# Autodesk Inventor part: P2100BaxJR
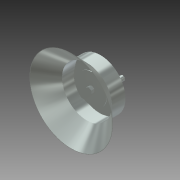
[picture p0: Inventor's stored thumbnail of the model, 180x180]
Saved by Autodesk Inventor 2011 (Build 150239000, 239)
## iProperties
Created: 2014-07
Part Number: P2100BaxJR
Document SubType Name: Modeling
Designer: Evgeny
Density: 1 g/cm^3
Author: Evgeny
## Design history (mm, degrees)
sketch "Эскиз1"
  geometry: L1 (31, 26.833)-(31, -26.833); L2 (-31, -26.833)-(-31, 26.833); C1 r 1.35 at (15, -26); A1 r 41 centre (0, 0) between (31, 26.833) and (-31, 26.833); A2 r 41 centre (0, 0) between (-31, -26.833) and (31, -26.833); 1 further point
  constraints: 4 end point, 4 point on circle, 3 centre point, 1 coincident, 1 parallel
  dimensions: "d1" = 62 distance between parallel lines of L1 L2; "d2" = 31 distance from line of L2 point (0, 0); "d3" = 41 radius of A1; "d4" = 41 radius of A2; "d7" = 2.7 diameter of C1; "d9" = 26 vertical distance of point (0, 0) C1.centre; "d50" = 15 horizontal distance of C1.centre point (0, 0)
extrude "Выдавливание1" new body sketch "Эскиз1" distance "d10" = 1; taper "d11" = 0 deg
sketch "Эскиз2"
  geometry: C1 r 4 at (0, 0); A1 r 41 centre (0, 0) between (31, 26.833) and (-31, 26.833) reference
  constraints: 1 centre point, 1 coincident
  dimensions: "d12" = 8 diameter of C1
extrude "Выдавливание2" join sketch "Эскиз2" distance "d13" = 6; taper "d14" = 0 deg
sketch "Эскиз3"
  geometry: C1 r 4 at (0, 0) reference; C2 r 28 at (0, 0)
  constraints: 1 centre point, 1 coincident
  dimensions: "d15" = 56 diameter of C2
extrude "Выдавливание3" join sketch "Эскиз3" distance "d16" = 1; taper "d17" = 0 deg
sketch "Эскиз4"
  geometry: L1 (5.774, 0)-(2.887, -5); L2 (2.887, -5)-(-2.887, -5); L3 (-2.887, -5)-(-5.774, 0); L4 (-5.774, 0)-(-2.887, 5); L5 (-2.887, 5)-(2.887, 5); L6 (2.887, 5)-(5.774, 0); C1 r 28 at (0, 0) reference; 1 further point
  constraints: 12 end point, 1 coincident, 13 other
  dimensions: "d18" = 10 distance between parallel lines of L2 L5
extrude "Выдавливание4" join sketch "Эскиз4" distance "d19" = 6; taper "d20" = 0 deg
sketch "Эскиз5"
  geometry: C1 r 4 at (0, 0); A1 r 41 centre (0, 0) between (31, 26.833) and (-31, 26.833) reference
  constraints: 1 centre point, 1 coincident
  dimensions: "d21" = 8 diameter of C1
extrude "Выдавливание5" join sketch "Эскиз5" distance "d22" = 7; taper "d23" = 0 deg
sketch "Эскиз6"
  geometry: C1 r 4 at (0, 0) reference; C2 r 47.5 at (0, 0); C3 r 4 at (-15, -26)
  constraints: 2 centre point, 1 coincident
  dimensions: "d24" = 95 diameter of C2; "d33" = 8 diameter of C3; "d52" = 26 vertical distance of C1.centre C3.centre; "d53" = 15 horizontal distance of C1.centre C3.centre
extrude "Выдавливание11" join sketch "Эскиз6" distance "d38" = 1.5; taper "d39" = 0 deg
sketch "Эскиз9"
  geometry: L1 (5.774, 0)-(2.887, -5); L2 (2.887, -5)-(-2.887, -5); L3 (-2.887, -5)-(-5.774, 0); L4 (-5.774, 0)-(-2.887, 5); L5 (-2.887, 5)-(2.887, 5); L6 (2.887, 5)-(5.774, 0); C1 r 47.5 at (0, 0) reference; 1 further point
  constraints: 12 end point, 1 coincident, 13 other
  dimensions: "d40" = 10 distance between parallel lines of L2 L5
extrude "Выдавливание12" join sketch "Эскиз9" distance "d41" = 6; taper "d42" = 0 deg
sketch "Эскиз10"
  geometry: C1 r 3 at (0, 0); 1 further point
  constraints: 1 centre point, 1 coincident
  dimensions: "d43" = 6 diameter of C1
extrude "Выдавливание13" join sketch "Эскиз10" distance "d44" = 6; taper "d45" = 0 deg
extrude "Выдавливание14" join sketch "Эскиз1" distance "d46" = 2; taper "d48" = 0 deg; dims "d47" = 24.5, "d49" = 0
sketch "Эскиз12"
  geometry: L1 (-47, 17.213)-(-78, 47); L2 (-78, 47)-(-78.722, 47); L3 (-78.722, 47)-(-47.5, 17); L4 (0, -19.6)-(0, 58.1) reference; L5 (-47, 17)-(-47, -8.5); L6 (-47, -8.5)-(-47.5, -8.5); L7 (-47.5, -8.5)-(-47.5, 17); L8 (-47, 17)-(-47, 17.213); 1 further point
  constraints: 14 end point, 3 parallel, 1 horizontal
  dimensions: "d65" = 0.5 distance between parallel lines of L5 L7; "d66" = 17 vertical distance of L3.end point (0, 0); "d67" = 25.5 distance from line of L6 L3.end; "d68" = 47.5 distance from line of point (0, 0) L7; "d69" = 30 distance from line of L2 L3.end; "d71" = 0.5 distance between parallel lines of L3 L1; "d72" = 31 distance from line of L5 L1.end
revolve "Вращение1" sketch "Эскиз12" stored, may be unused: angle "d64" = 90 deg
sketch "Эскиз13"
  geometry: C1 r 4 at (-15, -26) reference; C2 r 4.5 at (-15, -26)
  constraints: 1 centre point, 1 coincident
  dimensions: "d73" = 9 diameter of C2
extrude "Выдавливание16" join sketch "Эскиз13" distance "d74" = 16; taper "d75" = 0 deg
node "Твердое тело1"
other parameters: "d0" = 82
